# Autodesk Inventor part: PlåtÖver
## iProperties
Shininess: 64.0
Length Units: 11269
Angle Units: 11279
Time Units: 11290
Mass Units: 11283
Length Display Precision: 3
Angle Display Precision: 2
Compacted: True
Created: 2004-01
Part Number: PlåtÖver
Material: Steel, Mild
Document SubType Name: Modeling
Designer: Administratör
Manufacturer: Standard
Standards Organization: Custom
Density: 0.0
Volumn: 0.0
Area: 0.0
PropertySet Name: Model Information
Control State: 0
Master: False
Checked Out: False
Author: Administratör
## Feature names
1. Extrusion1
